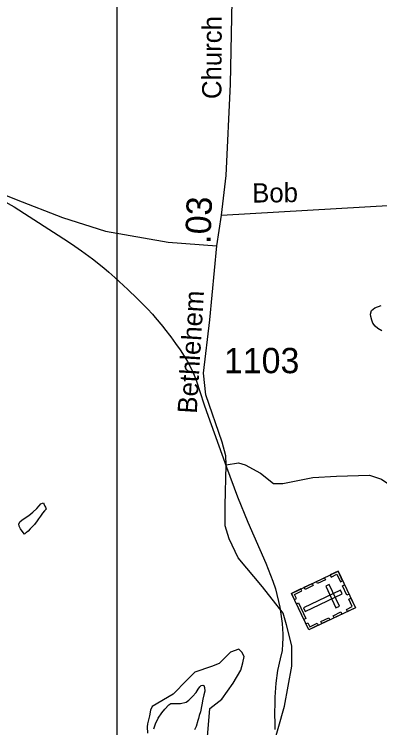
# Model space of a CAD drawing. Extents: x 2126262 to 2293712, y 749403 to 919119.
# Drawn here: x 2189186 to 2190988, y 799144 to 802665 of the extents above; entities that cross this region are included whole.
import ezdxf

# ---------------------------------------------------------------- set-up
doc = ezdxf.new("R2010")
doc.units = 0
for name, color, linetype in [('Exist Cultural Cemetery CELL', 7, 'Continuous'), ('Exist Hydrographic Misc Water Feature', 7, 'Continuous'), ('Exist Hydrographic Pond Under 1500 Sq Ft', 7, 'Continuous'), ('Exist Road Non-System Type 51', 7, 'Continuous'), ('Exist Road Secondary Mileage Hundredths English Label', 7, 'Continuous'), ('Exist Road Secondary Type 51 Attributed', 7, 'Continuous'), ('Exist Road Secondary Type 51 Label', 7, 'Continuous'), ('Exist Road Secondary Type 51 Number Label', 7, 'Continuous'), ('Map Preparation Inset Cut Line', 7, 'Continuous')]:
    doc.layers.add(name, color=color, linetype=linetype)

msp = doc.modelspace()

# ---------------------------------------------------------------- linework, layer by layer
at = {"layer": 'Exist Cultural Cemetery CELL'}
for points in [[(2190782.5, 799916.2), (2190867.9, 799736.4), (2190637.8, 799627.2), (2190552.5, 799807.1)], [(2190743.4, 799897.7), (2190748.2, 799887.4), (2190777.3, 799901.2), (2190794.7, 799864.6), (2190804.8, 799869.3), (2190782.5, 799916.2)], [(2190676.4, 799865.9), (2190715.5, 799884.5), (2190720.4, 799874.2), (2190681.3, 799855.6)], [(2190566.7, 799777.2), (2190577.1, 799782.1), (2190567.6, 799802), (2190604.1, 799819.3), (2190599.4, 799829.4), (2190552.5, 799807.1)], [(2190615.6, 799837.1), (2190654.8, 799855.7), (2190659.6, 799845.4), (2190620.5, 799826.8)], [(2190738.5, 799850.2), (2190721.6, 799842.2), (2190772.1, 799735.8), (2190789, 799743.8)], [(2190814.2, 799849.3), (2190836.5, 799802.5), (2190826.2, 799797.6), (2190803.9, 799844.4)], [(2190802.8, 799805.2), (2190794.8, 799822.1), (2190611.6, 799735.1), (2190619.6, 799718.2)], [(2190587.5, 799760.1), (2190623.8, 799683.4), (2190613.6, 799678.5), (2190577.2, 799755.2)], [(2190828.7, 799717.7), (2190823.8, 799728), (2190852.9, 799741.8), (2190835.5, 799778.4), (2190845.6, 799783.2), (2190867.8, 799736.3)], [(2190757.8, 799696.7), (2190796.9, 799715.3), (2190801.8, 799705), (2190762.7, 799686.4)], [(2190623.6, 799657.1), (2190634, 799662.1), (2190643.4, 799642.2), (2190679.9, 799659.5), (2190684.7, 799649.5), (2190637.8, 799627.2)], [(2190698.2, 799668.5), (2190737.4, 799687), (2190742.2, 799676.7), (2190703.1, 799658.2)]]:
    msp.add_lwpolyline(points, close=True, dxfattribs=at)
at = {"layer": 'Exist Hydrographic Misc Water Feature'}
for p, q in [((2190032.1, 800963.8), (2190040.3, 800951)), ((2190470.7, 799152.4), (2190471.1, 799135.7))]:
    msp.add_line(p, q, dxfattribs=at)
for points in [[(2189096.3, 801758.6), (2189129.3, 801745.2), (2189185.5, 801714.8), (2189453.5, 801540.9), (2189484.6, 801519.5)], [(2189096.3, 801758.6), (2189129.3, 801745.2), (2189185.5, 801714.8), (2189453.5, 801540.9), (2189484.6, 801519.5)], [(2189484.6, 801519.5), (2189517.2, 801497.2), (2189571.4, 801457.5)], [(2189484.6, 801519.5), (2189517.2, 801497.2), (2189571.4, 801457.5)], [(2189571.4, 801457.5), (2189627.1, 801412.9), (2189651.5, 801391.8)], [(2189571.4, 801457.5), (2189627.1, 801412.9), (2189651.5, 801391.8)], [(2189651.5, 801391.8), (2189681.5, 801366), (2189745.3, 801306.1)], [(2189651.5, 801391.8), (2189681.5, 801366), (2189745.3, 801306.1)], [(2189745.3, 801306.1), (2189792.2, 801262), (2189805.3, 801248.9)], [(2189745.3, 801306.1), (2189792.2, 801262), (2189805.3, 801248.9)], [(2189805.3, 801248.9), (2189843.3, 801210.8), (2189867.1, 801184.4)], [(2189805.3, 801248.9), (2189843.3, 801210.8), (2189867.1, 801184.4)], [(2190998.5, 801101.8), (2190978.4, 801113.7), (2190966.1, 801125.6), (2190954.2, 801139.6), (2190948.3, 801155.5), (2190944, 801173.4), (2190941.9, 801185.4), (2190947.7, 801203.5), (2190963.7, 801215.5), (2190995.5, 801227.8)], [(2189867.1, 801184.4), (2189881.2, 801168.7), (2189918.3, 801124.5), (2189927.3, 801112.6)], [(2189867.1, 801184.4), (2189881.2, 801168.7), (2189918.3, 801124.5), (2189927.3, 801112.6)], [(2189927.3, 801112.6), (2189957.3, 801073.1), (2189980.7, 801040.4)], [(2189927.3, 801112.6), (2189957.3, 801073.1), (2189980.7, 801040.4)], [(2189980.7, 801040.4), (2190003.2, 801008.7), (2190032.1, 800963.8)], [(2189980.7, 801040.4), (2190003.2, 801008.7), (2190032.1, 800963.8)], [(2190040.3, 800951), (2190066.4, 800900.6), (2190076.2, 800874.8)], [(2190040.3, 800951), (2190066.4, 800900.6), (2190076.2, 800874.8)], [(2190076.2, 800874.8), (2190084.2, 800854), (2190121.3, 800742.7)], [(2190076.2, 800874.8), (2190084.2, 800854), (2190121.3, 800742.7)], [(2190121.3, 800742.7), (2190134.2, 800704.1), (2190232.3, 800429.2)], [(2190121.3, 800742.7), (2190134.2, 800704.1), (2190232.3, 800429.2)], [(2190232.3, 800429.2), (2190287.2, 800283), (2190338.3, 800157.9), (2190426.2, 799956.5), (2190437.7, 799926.9)], [(2190232.3, 800429.2), (2190287.2, 800283), (2190338.3, 800157.9), (2190426.2, 799956.5), (2190437.7, 799926.9)], [(2189285.9, 800146.2), (2189263.8, 800126), (2189253.7, 800114.2), (2189245.9, 800108.1), (2189242.3, 800105.8), (2189235.7, 800099.9), (2189224, 800113.8), (2189215.8, 800126), (2189209.7, 800137.9), (2189207.8, 800149.9), (2189215.4, 800161.8), (2189229.8, 800173.8), (2189257.4, 800192), (2189277.5, 800208.4), (2189297.2, 800226.5), (2189308.9, 800238.5), (2189316.9, 800248.7), (2189324.9, 800252.8), (2189329, 800254.6), (2189331, 800248.6), (2189337, 800236.7), (2189339, 800232.8), (2189342.7, 800222.8), (2189335.1, 800214.7), (2189325.5, 800202.7), (2189315.5, 800188.4), (2189305.4, 800174.5), (2189295.4, 800160.2), (2189287.8, 800152.4), (2189285.9, 800146.2)], [(2190437.7, 799926.9), (2190461.3, 799866.8), (2190473.2, 799829.3), (2190495.1, 799738.3), (2190507, 799657.9), (2190509.5, 799605.8)], [(2190437.7, 799926.9), (2190461.3, 799866.8), (2190473.2, 799829.3), (2190495.1, 799738.3), (2190507, 799657.9), (2190509.5, 799605.8)], [(2190509.5, 799605.8), (2190510.3, 799586), (2190508.5, 799558)], [(2190509.5, 799605.8), (2190510.3, 799586), (2190508.5, 799558)], [(2190508.5, 799558), (2190506.2, 799524.5), (2190497.2, 799484.4)], [(2190508.5, 799558), (2190506.2, 799524.5), (2190497.2, 799484.4)], [(2190497.2, 799484.4), (2190484.5, 799427.2), (2190476.3, 799364.3), (2190471.1, 799294.7), (2190470.1, 799255.2)], [(2190497.2, 799484.4), (2190484.5, 799427.2), (2190476.3, 799364.3), (2190471.1, 799294.7), (2190470.1, 799255.2)], [(2189874.6, 799138.8), (2189882.4, 799162.8), (2189896, 799190.8), (2189914, 799216.8), (2189927.5, 799235), (2189947.4, 799257.2), (2189957.3, 799263.4), (2189969.2, 799263.2), (2189983.7, 799263.5), (2190005.5, 799263.4), (2190033.6, 799269.7), (2190047.3, 799279.8), (2190065.1, 799297.8), (2190083, 799318.3), (2190092.8, 799334.2), (2190100.8, 799346), (2190107, 799352.4), (2190115, 799354.4), (2190120.9, 799352.3), (2190123, 799342.2), (2190125.2, 799324.4), (2190121.3, 799306.4), (2190115.2, 799284.2), (2190111.3, 799256.4), (2190103.5, 799222.3), (2190097.5, 799204.1), (2190093.8, 799190), (2190090.1, 799180.1), (2190082.2, 799150), (2190073.9, 799134.2)], [(2190470.1, 799255.2), (2190469.3, 799226.2), (2190470.7, 799152.4)], [(2190470.1, 799255.2), (2190469.3, 799226.2), (2190470.7, 799152.4)]]:
    msp.add_lwpolyline(points, dxfattribs=at)
at = {"layer": 'Exist Hydrographic Pond Under 1500 Sq Ft'}
msp.add_lwpolyline([(2190139.1, 799098.8), (2190150.3, 799238.8), (2190209.1, 799284.3), (2190265.2, 799364.2), (2190302.4, 799428.8), (2190312.4, 799464.3), (2190319, 799495.5), (2190307.9, 799517.7), (2190293.5, 799531), (2190252.4, 799516.6), (2190195.8, 799461), (2190159, 799446.6), (2190075.8, 799417.7), (2190035.9, 799378.8), (2189969.2, 799309.9), (2189864.9, 799248.8), (2189858.2, 799229.9), (2189852.6, 799202.1), (2189842.6, 799163.2), (2189841.5, 799147.7), (2189842.6, 799116.5)], dxfattribs=at)
at = {"layer": 'Exist Road Non-System Type 51'}
msp.add_lwpolyline([(2190231.2, 800441.7), (2190291.7, 800451.8), (2190323.8, 800442), (2190399.2, 800400.1), (2190464.8, 800349.8), (2190509.4, 800348.4), (2190657.4, 800379.2), (2190774.6, 800384.8), (2190937.2, 800389.6), (2190997.2, 800370.1), (2191087.9, 800310), (2191139.5, 800257), (2191174.4, 800208.1), (2191245.6, 800152.2), (2191322.3, 800122.9), (2191429.1, 800122.2), (2191631.4, 800134.7), (2191832.4, 800168.3), (2191967.9, 800190.6)], dxfattribs=at)
at = {"layer": 'Exist Road Secondary Type 51 Attributed'}
msp.add_line((2190185.2, 801522.3), (2190207.7, 801672.9), dxfattribs=at)
for points in [[(2190207.7, 801672.9), (2190231.1, 801869.5), (2190252.7, 802319.9), (2190264.6, 802981.2), (2190286.2, 803413.4), (2190290.4, 803567), (2190296, 803733.2), (2190289.7, 803884.7), (2190240.9, 804250.6), (2190203.2, 804483.5), (2190178.8, 804695.1)], [(2186655.1, 802272.2), (2187667.7, 802014.9), (2187792.1, 801990.1), (2188124.2, 801973.3), (2188428.4, 801951), (2188727, 801906.3), (2188934.9, 801854.6), (2189194.5, 801751.2), (2189423.3, 801661.9), (2189635.4, 801594.8), (2189943.8, 801540.4), (2190185.2, 801522.3)], [(2190207.7, 801672.9), (2191197.2, 801730.6), (2191504.2, 801740.4), (2191679.3, 801739.7), (2191800.7, 801750.9), (2192175.4, 801839.6), (2192392, 801905.5)], [(2190455.1, 799030.3), (2190517.9, 799251), (2190554.9, 799448.6), (2190554.9, 799547.8), (2190528.4, 799652.6), (2190511.7, 799709.8), (2190410.5, 799839), (2190290.5, 799982.9), (2190245.8, 800076.5), (2190224.9, 800140.7), (2190225.6, 800240.6), (2190231.2, 800441.7), (2190228.4, 800485), (2190210.9, 800552.7), (2190130.7, 800786.7), (2190119.5, 800894.2), (2190149.5, 801156.1), (2190185.2, 801522.3)]]:
    msp.add_lwpolyline(points, dxfattribs=at)
at = {"layer": 'Map Preparation Inset Cut Line'}
msp.add_lwpolyline([(2168450.6, 811054.9), (2189691.2, 811054.9), (2189691.2, 794536.3), (2179257.6, 795892.5)], close=True, dxfattribs=at)

# ---------------------------------------------------------------- texts
at = {"layer": 'Exist Road Secondary Mileage Hundredths English Label'}
msp.add_text('.03', height=125, rotation=87.8335, dxfattribs=at).set_placement((2190152.8, 801530.6))
at = {"layer": 'Exist Road Secondary Type 51 Label'}
for s, rotation, p in [('Church', 89.7349, (2190206.9, 802245.9)), ('Bob', 0.6473, (2190359.3, 801735.3)), ('Bethlehem', 86.6068, (2190085.4, 800692.2))]:
    msp.add_text(s, height=95, rotation=rotation, dxfattribs=at).set_placement(p)
at = {"layer": 'Exist Road Secondary Type 51 Number Label'}
msp.add_text('1103', height=125, dxfattribs=at).set_placement((2190219.8, 800893.4))

doc.saveas('drawing.dxf')
